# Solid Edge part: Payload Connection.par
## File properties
Author: hullrw
Template: ansi part.par
Last saved by: hullrw
Revision: 1
Application: Solid Edge
Density: 0.02568650461 lbm/in^3
Accuracy: 0.990
Material: Wood, Birch
Face Style: Tan
Fill Style: Wood (Radial)
Virtual Style: Polished paper birch
Coef. of Thermal Exp: 0.0
Thermal Conductivity: 0.0
Specific Heat: 0.0
Modulus of Elasticity: 0.0
Poisson's Ratio: 0.0
Yield Stress: 0.0
Ultimate Stress: 0.0
Elongation: 0.0
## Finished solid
Body 1: solid body, 45 faces, 127 edges, 82 vertices.
  Faces by surface: plane 35, cylinder 10
  Edges by curve: line 107, circle 20
Bounding box of the edges (mm): 3.175 x 154.055 x 113.419, from (-3.175, -77.0278, -56.7093) to (0, 77.0278, 56.7093).
Cylindrical faces by radius (mm): R4.8514 x2, R6.35 x1, R12.7 x7
Planar faces by outward normal: +x 1, -x 1, oblique 33
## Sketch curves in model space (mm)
line (0, -46.2244, -3.4009) -> (0, -42.6873, -2.9039)
line (0, -42.6873, -2.9039) -> (0, -43.1069, 0.2433)
line (0, -43.1069, 0.2433) -> (0, -39.9628, 0.6853)
line (0, -39.9628, 0.6853) -> (0, -39.5432, -2.4621)
line (0, -39.5432, -2.4621) -> (0, -8.89, 1.8452)
line (0, -8.89, 1.8452) -> (0, -9.3308, 4.9894)
line (0, -9.3308, 4.9894) -> (0, -6.1816, 5.4319)
line (0, -6.1816, 5.4319) -> (0, -5.7459, 2.287)
line (0, -5.7459, 2.287) -> (0, -2.2087, 2.784)
line (0, -2.2087, 2.784) -> (0, -1.7491, -0.4837)
line (0, -1.7491, -0.4837) -> (0, -45.7647, -6.6712)
line (0, -46.2263, -3.4012) -> (0, -45.7647, -6.6712)
line (0, -8.3193, 46.2647) -> (0, -7.8577, 42.9947)
line (0, -52.3349, 40.0773) -> (0, -8.3193, 46.2647)
line (0, -11.3967, 42.4974) -> (0, -10.9771, 39.3503)
line (0, -10.9771, 39.3503) -> (0, -14.1212, 38.9083)
line (0, -14.1212, 38.9083) -> (0, -14.5409, 42.0556)
line (0, -14.5409, 42.0556) -> (0, -45.194, 37.7484)
line (0, -45.194, 37.7484) -> (0, -44.7532, 34.6041)
line (0, -44.7532, 34.6041) -> (0, -47.9024, 34.1616)
line (0, -47.9024, 34.1616) -> (0, -48.3381, 37.3066)
line (0, -48.3381, 37.3066) -> (0, -51.8753, 36.8096)
line (0, -51.8753, 36.8096) -> (0, -52.3349, 40.0773)
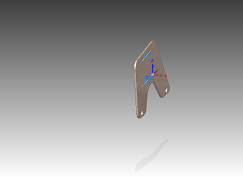
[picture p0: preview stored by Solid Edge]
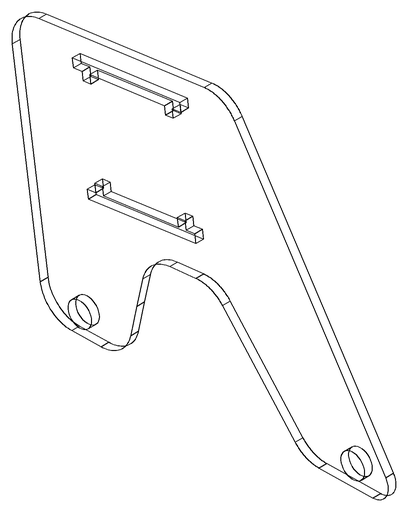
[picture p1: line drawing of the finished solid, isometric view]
